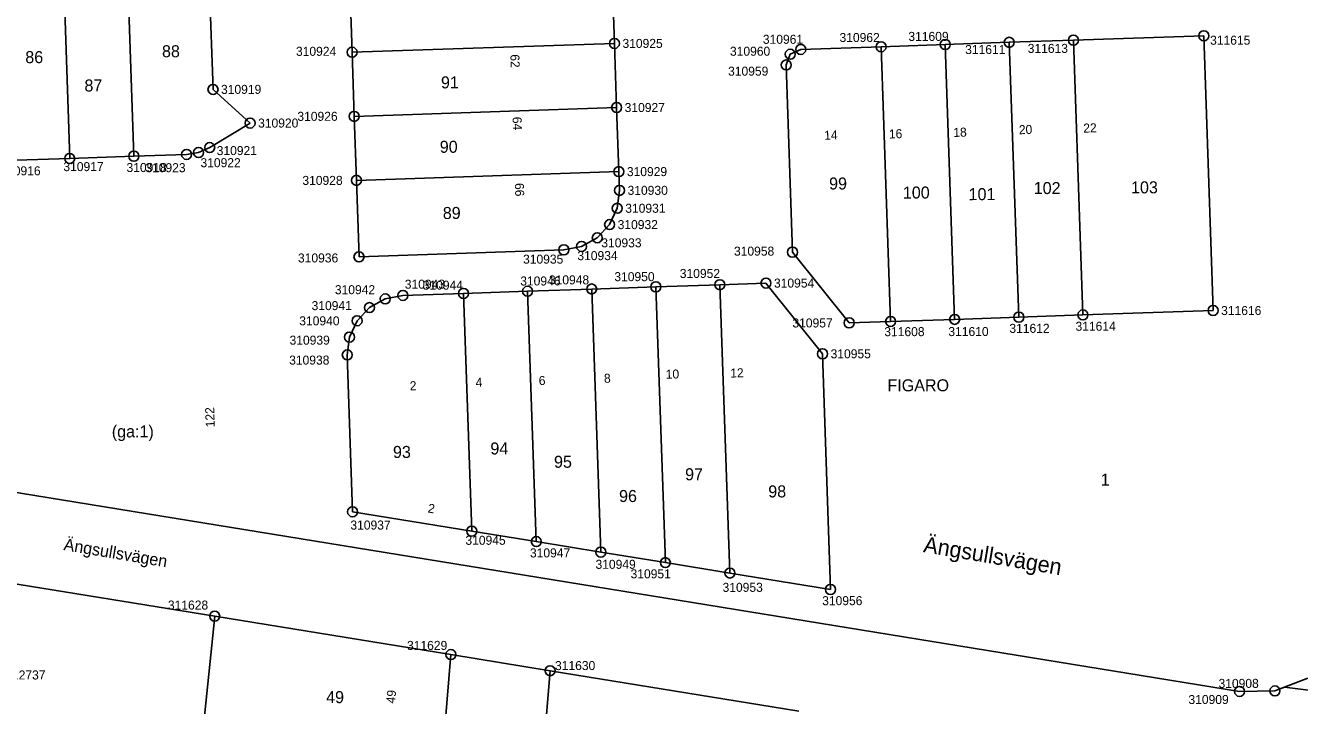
# Model space of a CAD drawing. Extents: x 141995 to 152570, y 6580184 to 6586000.
# Drawn here: x 142245.6 to 142372.8, y 6585177.1 to 6585245 of the extents above; entities that cross this region are included whole.
import ezdxf

# ---------------------------------------------------------------- set-up
doc = ezdxf.new("R2010")
doc.units = 0
for name, color, linetype in [('Level 10', 7, 'Continuous'), ('Level 42', 7, 'Continuous'), ('Level 43', 7, 'Continuous'), ('Level 5', 7, 'Continuous'), ('Level 51', 7, 'Continuous'), ('Level 53', 7, 'Continuous'), ('Level 54', 7, 'Continuous'), ('Level 55', 7, 'Continuous'), ('Level 58', 7, 'Continuous'), ('Level 59', 7, 'Continuous'), ('Level 6', 7, 'Continuous'), ('Level 7', 7, 'Continuous')]:
    doc.layers.add(name, color=color, linetype=linetype)

msp = doc.modelspace()

# ---------------------------------------------------------------- linework, layer by layer
at = {"layer": 'Level 10'}
for centre in [(142363.23, 6585244.02), (142304.42, 6585243.25), (142323.01, 6585242.65), (142331.03, 6585242.92), (142337.43, 6585243.14), (142343.82, 6585243.36), (142350.22, 6585243.58), (142278.24, 6585242.37), (142321.96, 6585242.17), (142321.56, 6585241.1), (142264.36, 6585238.66), (142304.64, 6585236.85), (142268.06, 6585235.3), (142278.45, 6585235.97), (142264.03, 6585232.85), (142250.06, 6585231.77), (142256.46, 6585231.99), (142261.72, 6585232.17), (142262.92, 6585232.36), (142304.86, 6585230.45), (142278.67, 6585229.58), (142304.93, 6585228.58), (142304.7, 6585226.79), (142303.94, 6585225.16), (142302.71, 6585223.85), (142299.37, 6585222.64), (142301.14, 6585222.98), (142322.19, 6585222.41), (142278.93, 6585221.94), (142295.75, 6585218.51), (142302.15, 6585218.73), (142308.55, 6585218.95), (142314.94, 6585219.16), (142319.54, 6585219.32), (142281.55, 6585217.74), (142283.31, 6585218.09), (142289.36, 6585218.29), (142279.97, 6585216.87), (142344.77, 6585215.92), (142351.17, 6585216.14), (142364.16, 6585216.58), (142278.74, 6585215.56), (142327.84, 6585215.35), (142331.98, 6585215.49), (142338.37, 6585215.7), (142277.98, 6585213.93), (142277.76, 6585212.15), (142325.19, 6585212.26), (142278.29, 6585196.49), (142290.18, 6585194.55), (142296.62, 6585193.51), (142303.06, 6585192.46), (142309.5, 6585191.41), (142315.94, 6585190.37), (142325.98, 6585188.73), (142264.53, 6585186.06), (142288.1, 6585182.23), (142298, 6585180.62), (142366.8, 6585178.55), (142370.33, 6585178.6)]:
    msp.add_circle(centre, 0.5, dxfattribs=at)
at = {"layer": 'Level 5'}
for points in [[(142200.33, 6585205.62), (142366.8, 6585178.55)], [(142243.77, 6585189.44), (142264.53, 6585186.06)], [(142264.53, 6585186.06), (142288.1, 6585182.23)], [(142288.1, 6585182.23), (142298, 6585180.62)], [(142298, 6585180.62), (142322.83, 6585176.58)], [(142371.29, 6585178.98), (142373.61, 6585179.88)], [(142370.33, 6585178.6), (142366.8, 6585178.55)], [(142371.29, 6585178.98), (142370.33, 6585178.6)]]:
    msp.add_lwpolyline(points, dxfattribs=at)
at = {"layer": 'Level 6'}
for points in [[(142200.33, 6585205.62), (142366.8, 6585178.55), (142370.33, 6585178.6), (142373.61, 6585179.88)], [(142322.83, 6585176.58), (142298, 6585180.62), (142288.1, 6585182.23), (142264.53, 6585186.06), (142243.77, 6585189.44)]]:
    msp.add_lwpolyline(points, dxfattribs=at)
at = {"layer": 'Level 7'}
for points in [[(142249.2, 6585257.39), (142250.06, 6585231.77)], [(142255.61, 6585257.33), (142256.46, 6585231.99)], [(142277.95, 6585250.92), (142278.24, 6585242.37)], [(142264.02, 6585248.66), (142264.36, 6585238.66)], [(142304.33, 6585246.07), (142304.42, 6585243.25)], [(142278.24, 6585242.37), (142304.42, 6585243.25)], [(142304.42, 6585243.25), (142304.64, 6585236.85)], [(142331.03, 6585242.92), (142337.43, 6585243.14)], [(142337.43, 6585243.14), (142343.82, 6585243.36)], [(142338.37, 6585215.7), (142337.43, 6585243.14)], [(142343.82, 6585243.36), (142350.22, 6585243.58)], [(142344.77, 6585215.92), (142343.82, 6585243.36)], [(142350.22, 6585243.58), (142363.23, 6585244.02)], [(142351.17, 6585216.14), (142350.22, 6585243.58)], [(142363.23, 6585244.02), (142364.16, 6585216.58)], [(142278.45, 6585235.97), (142278.24, 6585242.37)], [(142321.56, 6585241.1), (142321.96, 6585242.17)], [(142321.96, 6585242.17), (142323.01, 6585242.65)], [(142323.01, 6585242.65), (142331.03, 6585242.92)], [(142331.03, 6585242.92), (142331.98, 6585215.49)], [(142322.19, 6585222.41), (142321.56, 6585241.1)], [(142264.36, 6585238.66), (142268.06, 6585235.3)], [(142278.45, 6585235.97), (142304.64, 6585236.85)], [(142304.64, 6585236.85), (142304.86, 6585230.45)], [(142278.67, 6585229.58), (142278.45, 6585235.97)], [(142268.06, 6585235.3), (142264.03, 6585232.85)], [(142250.06, 6585231.77), (142243.66, 6585231.55)], [(142256.46, 6585231.99), (142250.06, 6585231.77)], [(142261.72, 6585232.17), (142256.46, 6585231.99)], [(142262.92, 6585232.36), (142261.72, 6585232.17)], [(142264.03, 6585232.85), (142262.92, 6585232.36)], [(142278.67, 6585229.58), (142304.86, 6585230.45)], [(142304.86, 6585230.45), (142304.93, 6585228.58)], [(142278.93, 6585221.94), (142278.67, 6585229.58)], [(142304.93, 6585228.58), (142304.7, 6585226.79)], [(142304.7, 6585226.79), (142303.94, 6585225.16)], [(142303.94, 6585225.16), (142302.71, 6585223.85)], [(142301.14, 6585222.98), (142299.37, 6585222.64)], [(142302.71, 6585223.85), (142301.14, 6585222.98)], [(142299.37, 6585222.64), (142278.93, 6585221.94)], [(142327.84, 6585215.35), (142322.19, 6585222.41)], [(142308.55, 6585218.95), (142314.94, 6585219.16)], [(142314.94, 6585219.16), (142319.54, 6585219.32)], [(142315.94, 6585190.37), (142314.94, 6585219.16)], [(142319.54, 6585219.32), (142325.19, 6585212.26)], [(142279.97, 6585216.87), (142281.55, 6585217.74)], [(142281.55, 6585217.74), (142283.31, 6585218.09)], [(142283.31, 6585218.09), (142289.36, 6585218.29)], [(142289.36, 6585218.29), (142295.75, 6585218.51)], [(142290.18, 6585194.55), (142289.36, 6585218.29)], [(142295.75, 6585218.51), (142302.15, 6585218.73)], [(142296.62, 6585193.51), (142295.75, 6585218.51)], [(142302.15, 6585218.73), (142308.55, 6585218.95)], [(142303.06, 6585192.46), (142302.15, 6585218.73)], [(142309.5, 6585191.41), (142308.55, 6585218.95)], [(142278.74, 6585215.56), (142279.97, 6585216.87)], [(142364.16, 6585216.58), (142351.17, 6585216.14)], [(142277.98, 6585213.93), (142278.74, 6585215.56)], [(142331.98, 6585215.49), (142327.84, 6585215.35)], [(142338.37, 6585215.7), (142331.98, 6585215.49)], [(142344.77, 6585215.92), (142338.37, 6585215.7)], [(142351.17, 6585216.14), (142344.77, 6585215.92)], [(142277.76, 6585212.15), (142277.98, 6585213.93)], [(142278.29, 6585196.49), (142277.76, 6585212.15)], [(142325.19, 6585212.26), (142325.98, 6585188.73)], [(142290.18, 6585194.55), (142278.29, 6585196.49)], [(142296.62, 6585193.51), (142290.18, 6585194.55)], [(142303.06, 6585192.46), (142296.62, 6585193.51)], [(142309.5, 6585191.41), (142303.06, 6585192.46)], [(142315.94, 6585190.37), (142309.5, 6585191.41)], [(142325.98, 6585188.73), (142315.94, 6585190.37)], [(142264.53, 6585186.06), (142263.36, 6585174.48)], [(142287.3, 6585172.53), (142288.1, 6585182.23)], [(142298, 6585180.62), (142297.04, 6585169.09)], [(142385.46, 6585177.2), (142371.29, 6585178.98)]]:
    msp.add_lwpolyline(points, dxfattribs=at)

# ---------------------------------------------------------------- texts
at = {"layer": 'Level 42'}
msp.add_text('Ängsullsvägen', height=1.2, rotation=350.4248, dxfattribs=at).set_placement((142249.4, 6585192.67))
at = {"layer": 'Level 43'}
msp.add_text('Ängsullsvägen', height=1.6, rotation=350.424, dxfattribs=at).set_placement((142335.18, 6585192.47))
at = {"layer": 'Level 51'}
for s, rotation, p in [('86', 0.0526, (142245.63, 6585241.28)), ('88', 0.0526, (142259.27, 6585241.87)), ('91', 0.0526, (142287.11, 6585238.76)), ('90', 0.0526, (142286.99, 6585232.33)), ('99', 0.0526, (142325.84, 6585228.66)), ('102', 0.0526, (142346.26, 6585228.21)), ('103', 0.0526, (142355.97, 6585228.28)), ('100', 0.0526, (142333.2, 6585227.76)), ('101', 0.0526, (142339.76, 6585227.6)), ('89', 0.0526, (142287.29, 6585225.72)), ('93', 0.0526, (142282.32, 6585201.86)), ('94', 0.0526, (142292.04, 6585202.21)), ('95', 0.0526, (142298.39, 6585200.88)), ('97', 0.0526, (142311.47, 6585199.63)), ('1', 0.0522, (142352.95, 6585199.09)), ('96', 0.0526, (142304.88, 6585197.46)), ('98', 0.0526, (142319.77, 6585197.92)), ('49', 0.0526, (142275.65, 6585177.38))]:
    msp.add_text(s, height=1.2, rotation=rotation, dxfattribs=at).set_placement(p)
msp.add_text('(ga:1)', height=1.2, dxfattribs=at).set_placement((142254.26, 6585203.91))
at = {"layer": 'Level 53'}
for s, rotation, p in [('311609', 0.0526, (142333.75, 6585243.5)), ('310925', 0.0526, (142305.22, 6585242.8)), ('310961', 0.0526, (142319.23, 6585243.21)), ('310962', 0.0526, (142326.88, 6585243.39)), ('311613', 0.0526, (142345.66, 6585242.3)), ('311615', 0.0526, (142363.86, 6585243.12)), ('310924', 0.0526, (142272.64, 6585242.01)), ('310960', 0.0526, (142315.95, 6585242.02)), ('311611', 0.0526, (142339.42, 6585242.19)), ('310959', 0.0526, (142315.76, 6585240.03)), ('310919', 0.0526, (142265.16, 6585238.21)), ('310927', 0.0526, (142305.44, 6585236.4)), ('310920', 0.0526, (142268.86, 6585234.85)), ('310926', 0.0526, (142272.78, 6585235.52)), ('310921', 0.0526, (142264.73, 6585232.1)), ('310922', 0.0526, (142263.11, 6585230.89)), ('310916', 0.0526, (142243.14, 6585230.08)), ('310917', 0.0526, (142249.43, 6585230.5)), ('310918', 0.0526, (142255.73, 6585230.41)), ('310923', 0.0526, (142257.61, 6585230.39)), ('310929', 0.0526, (142305.66, 6585230)), ('310928', 0.0526, (142273.28, 6585229.12)), ('310930', 0.0526, (142305.73, 6585228.13)), ('310931', 0.0526, (142305.5, 6585226.34)), ('310932', 0.0526, (142304.74, 6585224.71)), ('310933', 0.0526, (142303.11, 6585222.89)), ('310958', 0.0526, (142316.35, 6585222.06)), ('310936', 0.0526, (142272.84, 6585221.38)), ('310935', 0.0526, (142295.3, 6585221.26)), ('310934', 0.0526, (142300.72, 6585221.61)), ('310950', 0.0526, (142304.41, 6585219.51)), ('310952', 0.0526, (142310.94, 6585219.83)), ('310942', 0.0526, (142276.52, 6585218.21)), ('310943', 0.0526, (142283.5, 6585218.76)), ('310944', 0.0526, (142285.29, 6585218.66)), ('310946', 0.0526, (142295.02, 6585219.08)), ('310948', 0.0526, (142297.88, 6585219.19)), ('310954', 0.0526, (142320.34, 6585218.87)), ('310941', 0.0526, (142274.2, 6585216.62)), ('311616', 0.0526, (142364.96, 6585216.13)), ('310940', 0.0526, (142272.97, 6585215.1)), ('310957', 0.0526, (142322.18, 6585214.89)), ('311612', 0.0526, (142343.83, 6585214.35)), ('311614', 0.0526, (142350.43, 6585214.56)), ('310939', 0.0526, (142272, 6585213.17)), ('311608', 0.0526, (142331.35, 6585214.02)), ('311610', 0.0526, (142337.74, 6585214.03)), ('310955', 0.0526, (142325.99, 6585211.81)), ('310938', 0.0526, (142271.96, 6585211.18)), ('310937', 0.0526, (142278.07, 6585194.71)), ('310945', 0.0526, (142289.55, 6585193.19)), ('310947', 0.0526, (142295.99, 6585191.93)), ('310949', 0.0526, (142302.53, 6585190.79)), ('310951', 0.0526, (142306.03, 6585189.84)), ('310953', 0.0526, (142315.21, 6585188.49)), ('311628', 0.0526, (142259.86, 6585186.72)), ('310956', 0.0526, (142325.15, 6585187.16)), ('311629', 0.0526, (142283.72, 6585182.69)), ('311630', 0.0526, (142298.49, 6585180.68)), ('312737', 0.0526, (142243.63, 6585179.74)), ('310908', 0.0522, (142364.7, 6585178.9)), ('310909', 0.0522, (142361.7, 6585177.29))]:
    msp.add_text(s, height=0.9, rotation=rotation, dxfattribs=at).set_placement(p)
at = {"layer": 'Level 54'}
for s, rotation, p in [('62', 271.9317, (142294.03, 6585242.15)), ('64', 271.9317, (142294.25, 6585235.91)), ('14', 1.9505, (142325.36, 6585233.62)), ('16', 1.9505, (142331.82, 6585233.75)), ('18', 1.9505, (142338.25, 6585233.91)), ('20', 1.9505, (142344.79, 6585234.18)), ('22', 1.9505, (142351.22, 6585234.34)), ('66', 271.9317, (142294.48, 6585229.3)), ('6', 1.9775, (142296.88, 6585209.13)), ('8', 1.9775, (142303.39, 6585209.36)), ('10', 1.9775, (142309.55, 6585209.76)), ('12', 1.9775, (142315.99, 6585209.88)), ('2', 1.9775, (142284.01, 6585208.61)), ('4', 1.9775, (142290.58, 6585208.95)), ('122', 91.9947, (142264.54, 6585204.94)), ('49', 85.2686, (142282.53, 6585177.32))]:
    msp.add_text(s, height=0.9, rotation=rotation, dxfattribs=at).set_placement(p)
at = {"layer": 'Level 55'}
msp.add_text('2', height=0.9, rotation=350.7638, dxfattribs=at).set_placement((142285.75, 6585196.43))
at = {"layer": 'Level 58'}
msp.add_text('FIGARO', height=1.2, rotation=0.0526, dxfattribs=at).set_placement((142331.66, 6585208.51))
at = {"layer": 'Level 59'}
msp.add_text('87', height=1.2, rotation=0.0526, dxfattribs=at).set_placement((142251.53, 6585238.45))

doc.saveas('drawing.dxf')
